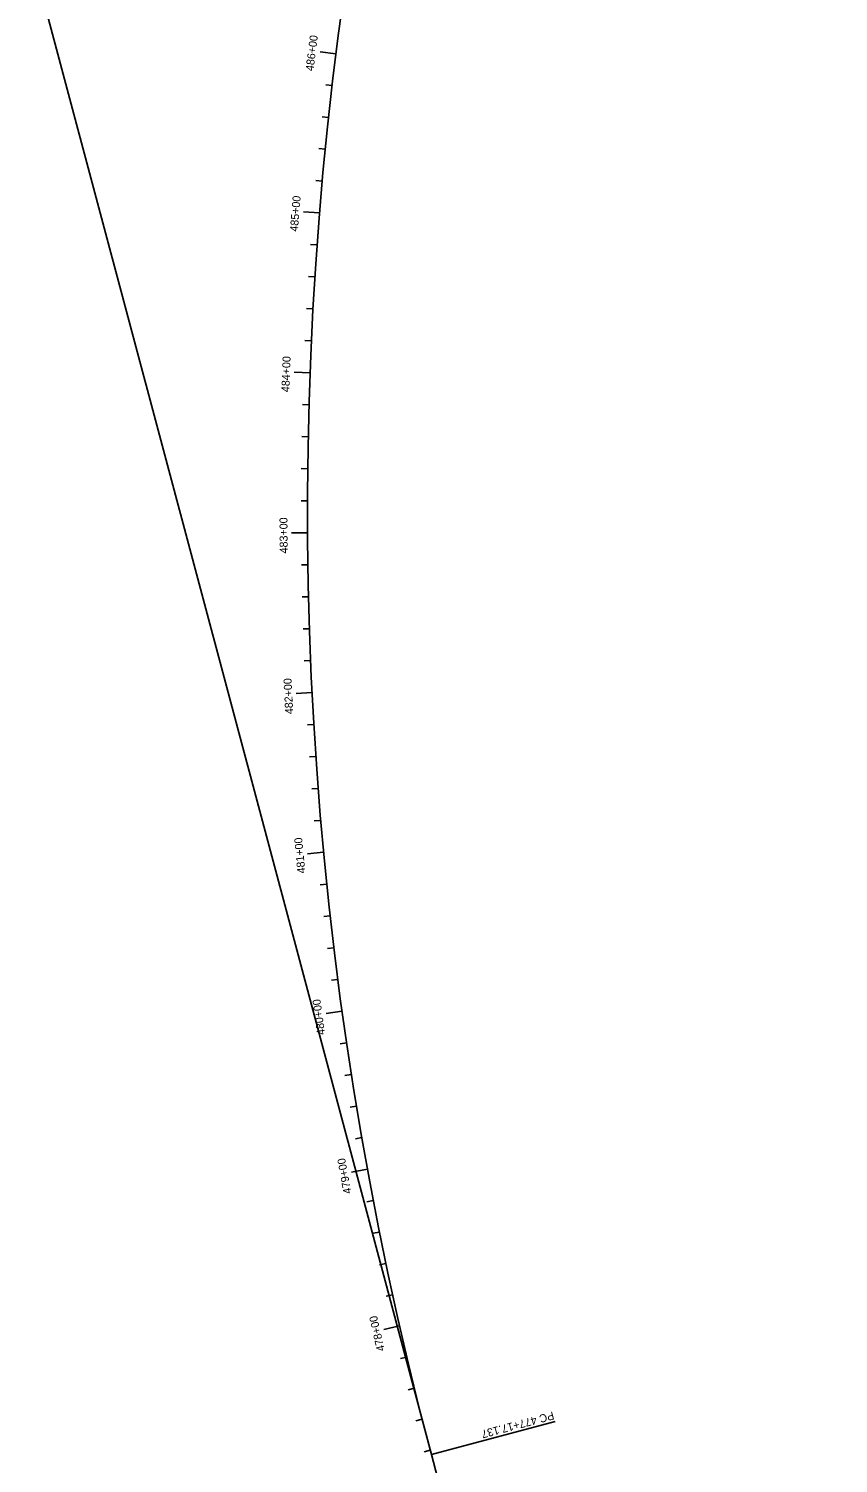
# Model space of a CAD drawing. Extents: x 187748 to 191086, y 249974 to 259749.
# Drawn here: x 189102 to 189607, y 254373 to 255270 of the extents above; entities that cross this region are included whole.
import ezdxf

# ---------------------------------------------------------------- set-up
doc = ezdxf.new("R2010")
doc.units = 0
doc.layers.add('BORDER', color=7, linetype='Continuous')

msp = doc.modelspace()

# ---------------------------------------------------------------- linework, layer by layer
at = {"layer": 'BORDER'}
for p, q in [((189293.48, 255253.96), (189283.56, 255255.2)), ((189291.08, 255234.1), (189287.11, 255234.56)), ((189288.86, 255214.22), (189284.88, 255214.65)), ((189286.81, 255194.33), (189282.83, 255194.72)), ((189284.93, 255174.42), (189280.95, 255174.78)), ((189283.23, 255154.49), (189273.26, 255155.3)), ((189281.7, 255134.55), (189277.71, 255134.84)), ((189280.34, 255114.59), (189276.35, 255114.85)), ((189279.16, 255094.63), (189275.17, 255094.85)), ((189278.16, 255074.65), (189274.16, 255074.84)), ((189277.33, 255054.67), (189267.33, 255055.05)), ((189276.67, 255034.68), (189272.67, 255034.8)), ((189276.18, 255014.69), (189272.19, 255014.77)), ((189275.88, 254994.69), (189271.88, 254994.74)), ((189275.74, 254974.69), (189271.74, 254974.7)), ((189275.78, 254954.69), (189265.78, 254954.63)), ((189276, 254934.69), (189272, 254934.63)), ((189276.39, 254914.7), (189272.39, 254914.6)), ((189276.95, 254894.71), (189272.95, 254894.58)), ((189277.69, 254874.72), (189273.69, 254874.55)), ((189278.6, 254854.74), (189268.61, 254854.24)), ((189279.69, 254834.77), (189275.7, 254834.53)), ((189280.95, 254814.81), (189276.96, 254814.54)), ((189282.39, 254794.86), (189278.4, 254794.56)), ((189283.99, 254774.93), (189280.01, 254774.59)), ((189285.78, 254755.01), (189275.82, 254754.07)), ((189287.74, 254735.1), (189283.76, 254734.69)), ((189289.87, 254715.22), (189285.89, 254714.77)), ((189292.17, 254695.35), (189288.2, 254694.87)), ((189294.65, 254675.5), (189290.68, 254674.99)), ((189297.3, 254655.68), (189287.39, 254654.31)), ((189300.12, 254635.88), (189296.16, 254635.3)), ((189303.12, 254616.11), (189299.17, 254615.49)), ((189306.29, 254596.36), (189302.34, 254595.71)), ((189309.63, 254576.64), (189305.69, 254575.95)), ((189313.14, 254556.95), (189303.3, 254555.15)), ((189316.82, 254537.29), (189312.9, 254536.54)), ((189320.68, 254517.67), (189316.76, 254516.88)), ((189324.71, 254498.08), (189320.79, 254497.26)), ((189328.9, 254478.52), (189325, 254477.67)), ((189333.27, 254459.01), (189323.52, 254456.78)), ((189337.81, 254439.53), (189333.92, 254438.6)), ((189342.52, 254420.09), (189338.64, 254419.13)), ((189347.4, 254400.69), (189343.52, 254399.7)), ((189353.18, 254378.57), (189430.48, 254399.2)), ((189352.44, 254381.34), (189348.58, 254380.31)), ((189591.47, 253485.34), (189353.18, 254378.57))]:
    msp.add_line(p, q, dxfattribs=at)
msp.add_lwpolyline([(189353.18, 254378.57), (189101.52, 255321.91), (189607.44, 256156.93)], dxfattribs=at)
msp.add_arc((191567.58, 254969.32), 2291.84, 148.78914, 194.93717, dxfattribs=at)

# ---------------------------------------------------------------- texts
for s, rotation, p in [('486+00', 82.8657, (189279.45, 255242.96)), ('485+00', 85.36569, (189269.7, 255142.65)), ('484+00', 87.86568, (189264.39, 255042.44)), ('483+00', 90.36567, (189263.37, 254941.75)), ('482+00', 92.86566, (189266.84, 254841.4)), ('481+00', 95.36565, (189274.47, 254742)), ('480+00', 97.86564, (189286.79, 254641.18)), ('479+00', 100.36563, (189303.25, 254542)), ('478+00', 102.86562, (189324.1, 254443.79)), ('PC 477+17.137', 194.93718, (189429.06, 254405.56))]:
    msp.add_text(s, height=5, rotation=rotation, dxfattribs=at).set_placement(p)

doc.saveas('drawing.dxf')
